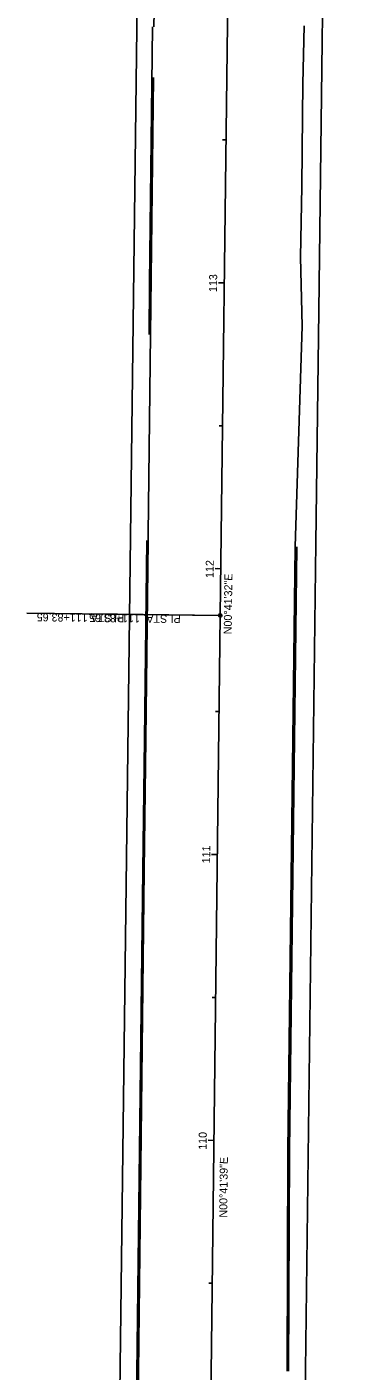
# Model space of a CAD drawing. Extents: x 1652464 to 1652601, y 605963 to 608618.
# Drawn here: x 1652484 to 1652601.5, y 606935 to 607405.2 of the extents above; entities that cross this region are included whole.
import ezdxf

# ---------------------------------------------------------------- set-up
doc = ezdxf.new("R2010")
doc.units = 0
for name, color, linetype in [('BD_X_Building', 7, 'Continuous'), ('GE_X_Cells', 7, 'Continuous'), ('PV_X_Curb', 7, 'Continuous'), ('PV_X_Steps', 7, 'Continuous'), ('PV_X_Walk', 7, 'Continuous'), ('SV_P_Mon_Cells_Set', 7, 'Continuous'), ('SV_X_Control_Cells_Found', 7, 'Continuous'), ('SV_X_Shot_Marker', 7, 'Continuous'), ('VG_X_Cells', 7, 'Continuous'), ('VG_X_Flower_Bed', 7, 'Continuous'), ('VG_X_Shrub_Line_Lt', 7, 'Continuous')]:
    doc.layers.add(name, color=color, linetype=linetype)

msp = doc.modelspace()

# ---------------------------------------------------------------- linework, layer by layer
at = {"layer": 'BD_X_Building'}
msp.add_lwpolyline([(1652507.27, 606201.32), (1652514.36, 606755.06), (1652515.19, 606820.32), (1652516.55, 606927.44), (1652537.47, 608602.59)], dxfattribs=at)
at = {"layer": 'GE_X_Cells'}
for p, q in [((1652528.55, 607405.21), (1652530.12, 607497.28)), ((1652580.68, 607385.24), (1652581.17, 607405.6)), ((1652580.68, 607385.24), (1652581.17, 607405.6)), ((1652580.68, 607385.24), (1652581.17, 607405.6)), ((1652580.68, 607385.24), (1652581.17, 607405.6)), ((1652580.68, 607385.24), (1652581.17, 607405.6)), ((1652580.68, 607385.24), (1652581.17, 607405.6)), ((1652526.33, 607207.74), (1652528.37, 607387.45)), ((1652580.53, 607374.27), (1652580.68, 607385.24)), ((1652580.53, 607374.27), (1652580.68, 607385.24)), ((1652580.53, 607374.27), (1652580.68, 607385.24)), ((1652580.53, 607374.27), (1652580.68, 607385.24)), ((1652580.53, 607374.27), (1652580.68, 607385.24)), ((1652580.53, 607374.27), (1652580.68, 607385.24)), ((1652580.32, 607349.32), (1652580.53, 607374.27)), ((1652580.32, 607349.32), (1652580.53, 607374.27)), ((1652580.32, 607349.32), (1652580.53, 607374.27)), ((1652580.32, 607349.32), (1652580.53, 607374.27)), ((1652580.32, 607349.32), (1652580.53, 607374.27)), ((1652580.32, 607349.32), (1652580.53, 607374.27)), ((1652579.83, 607324.71), (1652580.32, 607349.32)), ((1652579.83, 607324.71), (1652580.32, 607349.32)), ((1652579.83, 607324.71), (1652580.32, 607349.32)), ((1652579.83, 607324.71), (1652580.32, 607349.32)), ((1652579.83, 607324.71), (1652580.32, 607349.32)), ((1652579.83, 607324.71), (1652580.32, 607349.32)), ((1652580.41, 607300.56), (1652579.83, 607324.71)), ((1652580.41, 607300.56), (1652579.83, 607324.71)), ((1652580.41, 607300.56), (1652579.83, 607324.71)), ((1652580.41, 607300.56), (1652579.83, 607324.71)), ((1652580.41, 607300.56), (1652579.83, 607324.71)), ((1652580.41, 607300.56), (1652579.83, 607324.71)), ((1652578.04, 607223.49), (1652580.41, 607300.56)), ((1652578.04, 607223.49), (1652580.41, 607300.56)), ((1652578.04, 607223.49), (1652580.41, 607300.56)), ((1652578.04, 607223.49), (1652580.41, 607300.56)), ((1652578.04, 607223.49), (1652580.41, 607300.56)), ((1652578.04, 607223.49), (1652580.41, 607300.56)), ((1652525.7, 607156.04), (1652526.52, 607225.5)), ((1652575.48, 607012.07), (1652578.04, 607223.49)), ((1652575.48, 607012.07), (1652578.04, 607223.49)), ((1652575.48, 607012.07), (1652578.04, 607223.49)), ((1652575.48, 607012.07), (1652578.04, 607223.49)), ((1652575.48, 607012.07), (1652578.04, 607223.49)), ((1652575.48, 607012.07), (1652578.04, 607223.49)), ((1652525.17, 607110.06), (1652525.7, 607156.04)), ((1652522.93, 606920.85), (1652525.17, 607110.06)), ((1652575.19, 606934.98), (1652575.48, 607012.07)), ((1652575.19, 606934.98), (1652575.48, 607012.07)), ((1652575.19, 606934.98), (1652575.48, 607012.07)), ((1652575.19, 606934.98), (1652575.48, 607012.07)), ((1652575.19, 606934.98), (1652575.48, 607012.07)), ((1652575.19, 606934.98), (1652575.48, 607012.07))]:
    msp.add_line(p, q, dxfattribs=at)
msp.add_arc((1652546.46, 607220.77), 20, 179.3253, 179.3961, dxfattribs=at)
at = {"layer": 'PV_X_Curb'}
for p, q in [((1652551.76, 607199.34), (1652568.87, 608615.58)), ((1652578.54, 607223.33), (1652575.98, 607012.06)), ((1652540.01, 606229.06), (1652551.76, 607199.34)), ((1652575.7, 606934.99), (1652575.98, 607012.07))]:
    msp.add_line(p, q, dxfattribs=at)
at = {"layer": 'PV_X_Steps'}
msp.add_lwpolyline([(1652570.42, 606048.23), (1652570.59, 606069.16), (1652572.96, 606254.92), (1652575.24, 606433.07), (1652576.4, 606523.06), (1652578.06, 606652.96), (1652579.12, 606736.34), (1652580.12, 606814.04), (1652581.65, 606935.48), (1652585.26, 607224.58), (1652586.28, 607305.92), (1652588.75, 607503.82), (1652591.34, 607710.88), (1652594.35, 607951.77), (1652594.72, 607981.92), (1652597.89, 608234.94), (1652601.47, 608521.97)], dxfattribs=at)
at = {"layer": 'PV_X_Walk'}
for p, q in [((1652527.05, 607315.55), (1652528.05, 607405.21)), ((1652527.05, 607315.55), (1652528.05, 607405.21)), ((1652526.85, 607297.6), (1652527.05, 607315.55)), ((1652526.85, 607297.6), (1652527.05, 607315.55)), ((1652522.43, 606920.86), (1652524.67, 607110.06))]:
    msp.add_line(p, q, dxfattribs=at)
msp.add_lwpolyline([(1652524.67, 607110.06), (1652525.2, 607156.05), (1652526.02, 607225.51)], dxfattribs=at)
at = {"layer": 'SV_X_Control_Cells_Found'}
for p, q in [((1652551.76, 607199.34), (1652568.87, 608615.58)), ((1652551.76, 607199.34), (1652568.87, 608615.58)), ((1652540.01, 606229.06), (1652551.76, 607199.34)), ((1652540.01, 606229.06), (1652551.76, 607199.34))]:
    msp.add_line(p, q, dxfattribs=at)
at = {"layer": 'SV_X_Shot_Marker'}
for q in [(1652484.03, 607200.16), (1652506.76, 607199.88)]:
    msp.add_line((1652551.76, 607199.34), q, dxfattribs=at)
msp.add_circle((1652551.76, 607199.34), 0.6, dxfattribs=at)
msp.add_circle((1652551.76, 607199.34), 0.6, dxfattribs=at)
at = {"layer": 'VG_X_Cells'}
for p, q in [((1652553.77, 607365.67), (1652552.57, 607365.69)), ((1652553.17, 607315.68), (1652551.17, 607315.7)), ((1652552.56, 607265.68), (1652551.36, 607265.7)), ((1652551.96, 607215.68), (1652549.96, 607215.71)), ((1652551.35, 607165.69), (1652550.15, 607165.7)), ((1652550.75, 607115.69), (1652548.75, 607115.72)), ((1652550.14, 607065.7), (1652548.94, 607065.71)), ((1652549.54, 607015.7), (1652547.54, 607015.72)), ((1652548.93, 606965.7), (1652547.73, 606965.72))]:
    msp.add_line(p, q, dxfattribs=at)
at = {"layer": 'VG_X_Flower_Bed'}
msp.add_line((1652551.76, 607199.34), (1652506.76, 607199.88), dxfattribs=at)
msp.add_circle((1652551.76, 607199.34), 0.6, dxfattribs=at)
at = {"layer": 'VG_X_Shrub_Line_Lt'}
for p, q in [((1652553.17, 607315.68), (1652551.97, 607315.69)), ((1652551.96, 607215.68), (1652550.76, 607215.7)), ((1652550.75, 607115.69), (1652549.55, 607115.71)), ((1652549.54, 607015.7), (1652547.54, 607015.72))]:
    msp.add_line(p, q, dxfattribs=at)

# ---------------------------------------------------------------- texts
at = {"layer": 'SV_P_Mon_Cells_Set'}
for s, rotation, p in [('N00°41\'32"E', 89.3076, (1652555.78, 607192.72)), ('N00°41\'39"E', 89.3059, (1652554.19, 606988.66))]:
    msp.add_text(s, height=2.8, rotation=rotation, dxfattribs=at).set_placement(p)
at = {"layer": 'SV_X_Shot_Marker'}
for s, p in [('111+83.65', (1652505.32, 607199.87)), (' STA. ', (1652514.77, 607199.76)), ('PI', (1652518.17, 607199.72))]:
    msp.add_text(s, height=2.8, rotation=179.3076, dxfattribs=at).set_placement(p)
at = {"layer": 'VG_X_Cells'}
for s, rotation, p in [('113', 89.3076, (1652550.63, 607312.44)), ('112', 89.3076, (1652549.42, 607212.43)), ('111', 89.3059, (1652548.21, 607112.57)), ('110', 89.3059, (1652547, 607012.38))]:
    msp.add_text(s, height=2.8, rotation=rotation, dxfattribs=at).set_placement(p)
at = {"layer": 'VG_X_Flower_Bed'}
for s, p in [('111+83.65', (1652523.66, 607199.63)), (' STA. ', (1652534.24, 607199.5)), ('PI', (1652537.94, 607199.46))]:
    msp.add_text(s, height=2.8, rotation=179.3076, dxfattribs=at).set_placement(p)
at = {"layer": 'VG_X_Shrub_Line_Lt'}
msp.add_text('110', height=2.8, rotation=89.3059, dxfattribs=at).set_placement((1652546.95, 607012.38))

doc.saveas('drawing.dxf')
